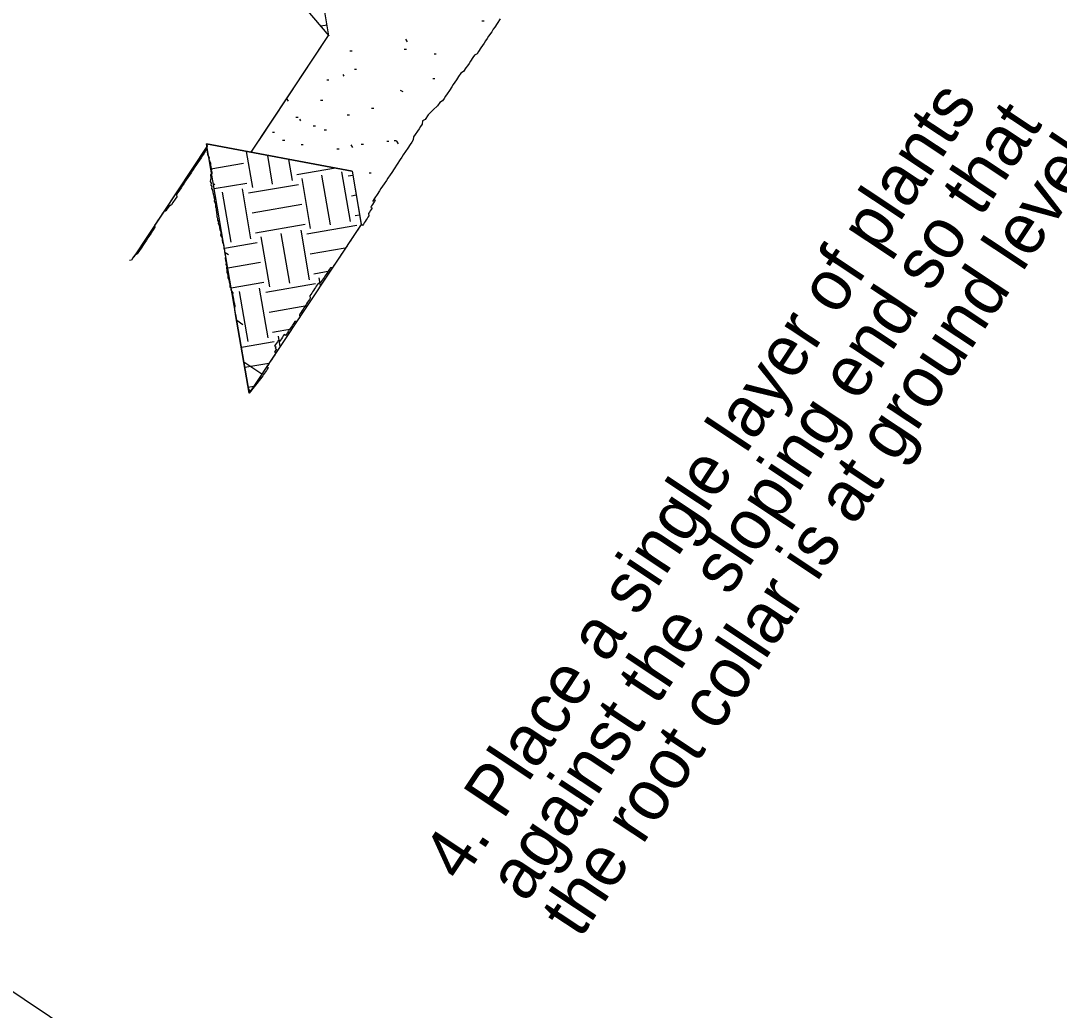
# Model space of a CAD drawing. Extents: x 561231 to 564240, y 590260 to 602519.
# Drawn here: x 563486.4 to 563562.9, y 590508.2 to 590581 of the extents above; entities that cross this region are included whole.
import ezdxf

# ---------------------------------------------------------------- set-up
doc = ezdxf.new("R2010")
doc.units = 0
doc.layers.add('Old_Level_1', color=7, linetype='Continuous')

msp = doc.modelspace()

# ---------------------------------------------------------------- linework, layer by layer
at = {"layer": 'Old_Level_1'}
for p, q in [((563509.071, 590579.938), (563501.981, 590621.124)), ((563509.071, 590579.938), (563501.981, 590621.124)), ((563496.058, 590595.222), (563509.071, 590579.938)), ((563520.329, 590581.03), (563520.495, 590581.03)), ((563508.372, 590580.744), (563508.372, 590580.745)), ((563508.935, 590580.727), (563508.469, 590580.646)), ((563503.345, 590571.354), (563509.043, 590579.944)), ((563503.908, 590572.202), (563509.047, 590579.95)), ((563503.908, 590572.202), (563509.047, 590579.95)), ((563509.062, 590579.95), (563509.071, 590579.938)), ((563509.062, 590579.95), (563509.071, 590579.938)), ((563509.065, 590579.929), (563509.065, 590579.93)), ((563509.065, 590579.93), (563509.065, 590579.929)), ((563514.858, 590579.495), (563514.737, 590579.686)), ((563510.61, 590578.824), (563510.775, 590578.824)), ((563514.612, 590578.945), (563514.778, 590578.945)), ((563516.814, 590578.599), (563516.979, 590578.6)), ((563510.187, 590576.967), (563510.106, 590577.095)), ((563510.945, 590577.467), (563511.11, 590577.467)), ((563508.904, 590576.702), (563509.069, 590576.702)), ((563516.711, 590576.789), (563516.877, 590576.789)), ((563514.319, 590575.938), (563514.503, 590575.844)), ((563506.096, 590575.124), (563505.974, 590575.315)), ((563508.448, 590575.188), (563508.614, 590575.188)), ((563506.632, 590573.934), (563506.797, 590573.934)), ((563510.418, 590574.105), (563510.583, 590574.105)), ((563512.213, 590574.611), (563512.379, 590574.61)), ((563507.011, 590573.664), (563506.931, 590573.791)), ((563507.918, 590573.303), (563508.084, 590573.304)), ((563504.9, 590572.836), (563505.065, 590572.837)), ((563508.715, 590573.021), (563508.88, 590573.021)), ((563500.077, 590571.764), (563494.701, 590563.659)), ((563500.083, 590571.773), (563494.707, 590563.668)), ((563500.083, 590571.773), (563494.707, 590563.668)), ((563503.193, 590553.625), (563500.055, 590571.97)), ((563500.055, 590571.97), (563510.776, 590569.961)), ((563510.776, 590569.961), (563500.055, 590571.97)), ((563505.648, 590572.254), (563505.813, 590572.254)), ((563507.012, 590571.937), (563507.178, 590571.938)), ((563510.824, 590571.712), (563510.703, 590571.903)), ((563511.447, 590571.947), (563511.612, 590571.946)), ((563513.323, 590572.178), (563513.488, 590572.178)), ((563513.884, 590572.224), (563514.049, 590572.225)), ((563514.196, 590571.981), (563514.074, 590572.171)), ((563503.456, 590568.765), (563502.999, 590571.418)), ((563504.923, 590569.018), (563504.56, 590571.126)), ((563509.651, 590571.611), (563509.817, 590571.611)), ((563502.774, 590570.536), (563500.371, 590570.122)), ((563506.389, 590569.271), (563506.12, 590570.833)), ((563509.544, 590570.191), (563506.693, 590569.7)), ((563507.723, 590565.751), (563507.091, 590569.418)), ((563509.19, 590566.004), (563508.558, 590569.671)), ((563510.656, 590566.257), (563510.025, 590569.923)), ((563510.827, 590569.657), (563510.486, 590569.598)), ((563510.776, 590569.961), (563511.434, 590566.049)), ((563510.782, 590569.97), (563511.44, 590566.058)), ((563510.782, 590569.97), (563511.44, 590566.058)), ((563512.021, 590569.845), (563512.186, 590569.845)), ((563500.554, 590569.053), (563500.657, 590568.985)), ((563503.026, 590569.069), (563500.622, 590568.655)), ((563503.323, 590564.993), (563502.691, 590568.66)), ((563506.819, 590568.967), (563503.153, 590568.335)), ((563501.856, 590564.741), (563501.224, 590568.408)), ((563511.074, 590568.19), (563510.738, 590568.132)), ((563507.072, 590567.501), (563503.405, 590566.869)), ((563511.321, 590566.722), (563510.991, 590566.665)), ((563511.434, 590566.049), (563503.193, 590553.625)), ((563507.324, 590566.034), (563503.658, 590565.402)), ((563507.648, 590561.964), (563507.017, 590565.63)), ((563511.113, 590565.958), (563507.447, 590565.327)), ((563504.715, 590561.458), (563504.084, 590565.124)), ((563506.182, 590561.711), (563505.55, 590565.377)), ((563503.78, 590564.695), (563501.37, 590564.28)), ((563510.276, 590564.304), (563507.699, 590563.86)), ((563501.421, 590563.98), (563501.664, 590563.819)), ((563504.033, 590563.228), (563501.621, 590562.812)), ((563509.145, 590562.599), (563507.951, 590562.393)), ((563504.285, 590561.762), (563501.872, 590561.346)), ((563508.447, 590561.547), (563508.35, 590562.11)), ((563503.115, 590557.434), (563502.484, 590561.1)), ((563504.581, 590557.686), (563503.95, 590561.353)), ((563508.078, 590561.66), (563504.411, 590561.028)), ((563507.449, 590560.041), (563504.664, 590559.562)), ((563502.276, 590558.982), (563502.723, 590558.686)), ((563506.318, 590558.337), (563504.917, 590558.095)), ((563505.038, 590557.388), (563502.62, 590556.971)), ((563505.472, 590557.061), (563505.342, 590557.817)), ((563502.8, 590555.923), (563504.131, 590555.04)), ((563504.641, 590555.809), (563502.871, 590555.504)), ((563503.51, 590554.104), (563503.122, 590554.037)), ((563503.144, 590553.909), (563503.309, 590553.8))]:
    msp.add_line(p, q, dxfattribs=at)
msp.add_lwpolyline([(563698.589, 591448.685), (563200.53, 590699.06), (563725.267, 590350.419), (564223.327, 591100.044)], close=True, dxfattribs=at)
for points in [[(563521.683, 590581.178), (563521.457, 590580.837), (563521.286, 590580.58), (563521.173, 590580.41), (563521.06, 590580.238), (563520.833, 590579.897), (563520.72, 590579.726), (563520.607, 590579.555), (563520.494, 590579.385), (563520.38, 590579.214), (563520.267, 590579.043), (563520.097, 590578.787), (563519.984, 590578.617), (563519.785, 590578.502), (563519.672, 590578.332), (563519.502, 590578.075), (563519.389, 590577.905), (563519.275, 590577.734), (563519.162, 590577.563), (563518.992, 590577.307), (563518.793, 590577.193), (563518.623, 590576.937), (563518.454, 590576.681), (563518.34, 590576.51), (563518.227, 590576.339), (563518.114, 590576.168), (563517.944, 590575.912), (563517.774, 590575.656), (563517.661, 590575.485), (563517.548, 590575.315), (563517.434, 590575.144), (563517.235, 590575.029), (563517.065, 590574.773), (563516.754, 590574.489), (563516.385, 590574.118), (563516.158, 590573.777), (563515.96, 590573.663), (563515.932, 590573.436), (563515.818, 590573.264), (563515.705, 590573.094), (563515.592, 590572.923), (563515.422, 590572.667), (563515.309, 590572.496), (563515.281, 590572.269), (563515.168, 590572.098), (563515.055, 590571.928), (563514.884, 590571.671), (563514.714, 590571.415), (563514.545, 590571.159), (563514.431, 590570.988), (563514.318, 590570.817), (563514.092, 590570.476), (563513.865, 590570.134), (563513.695, 590569.878), (563513.582, 590569.707), (563513.412, 590569.451), (563513.299, 590569.28), (563513.128, 590569.024), (563512.902, 590568.683), (563512.789, 590568.512), (563512.619, 590568.255), (563512.449, 590568), (563512.279, 590567.744)], [(563500.083, 590571.773), (563499.988, 590571.47), (563499.875, 590571.299), (563499.761, 590571.129), (563499.648, 590570.958), (563499.535, 590570.787), (563499.422, 590570.616), (563499.308, 590570.445), (563499.195, 590570.275), (563499.025, 590570.019), (563498.912, 590569.848), (563498.799, 590569.677), (563498.686, 590569.506), (563498.516, 590569.25), (563498.402, 590569.079), (563498.289, 590568.909), (563498.176, 590568.738), (563498.062, 590568.567), (563497.949, 590568.396), (563497.836, 590568.225), (563497.865, 590568.083), (563497.752, 590567.913), (563497.582, 590567.657), (563497.468, 590567.486), (563497.27, 590567.372), (563497.156, 590567.201), (563497.043, 590567.03), (563496.901, 590567.002), (563496.788, 590566.831), (563496.675, 590566.66), (563496.561, 590566.489), (563496.448, 590566.319), (563496.335, 590566.148), (563496.221, 590565.977), (563496.25, 590565.835), (563496.08, 590565.579), (563495.967, 590565.408), (563495.854, 590565.237), (563495.741, 590565.066), (563495.627, 590564.896), (563495.514, 590564.725), (563495.401, 590564.554), (563495.231, 590564.298), (563495.117, 590564.127), (563494.947, 590563.871), (563494.749, 590563.757), (563494.636, 590563.587), (563494.522, 590563.415), (563494.38, 590563.386), (563494.38, 590563.386)], [(563500.055, 590571.97), (563500.098, 590571.837), (563500.082, 590571.701), (563500.065, 590571.565), (563500.099, 590571.397), (563500.133, 590571.227), (563500.167, 590571.059), (563500.235, 590570.94), (563500.219, 590570.805), (563500.287, 590570.687), (563500.355, 590570.568), (563500.339, 590570.433), (563500.373, 590570.264), (563500.407, 590570.095), (563500.39, 590569.959), (563500.458, 590569.841), (563500.357, 590569.689), (563500.358, 590569.469), (563500.342, 590569.333), (563500.325, 590569.198), (563500.393, 590569.08), (563500.376, 590568.944), (563500.444, 590568.827), (563500.427, 590568.691), (563500.496, 590568.573), (563500.529, 590568.404), (563500.564, 590568.235), (563500.598, 590568.066), (563500.633, 590567.897), (563500.616, 590567.761), (563500.684, 590567.643), (563500.718, 590567.474), (563500.702, 590567.339), (563500.77, 590567.22), (563500.753, 590567.085), (563500.787, 590566.916), (563500.822, 590566.747), (563500.805, 590566.611), (563500.873, 590566.493), (563500.856, 590566.358), (563500.924, 590566.239), (563500.908, 590566.104), (563500.976, 590565.986), (563501.01, 590565.817), (563501.044, 590565.647), (563501.112, 590565.53), (563501.096, 590565.394), (563501.08, 590565.259), (563501.147, 590565.141), (563501.215, 590565.022), (563501.199, 590564.887), (563501.233, 590564.718), (563501.301, 590564.6), (563501.335, 590564.43), (563501.318, 590564.295), (563501.387, 590564.177), (563501.371, 590564.042), (563501.404, 590563.873), (563501.439, 590563.703), (563501.422, 590563.568), (563501.456, 590563.399), (563501.491, 590563.23), (563501.474, 590563.095), (563501.542, 590562.976), (563501.525, 590562.841), (563501.559, 590562.672), (563501.543, 590562.537), (563501.628, 590562.334), (563501.629, 590562.114), (563501.697, 590561.996), (563501.731, 590561.826), (563501.765, 590561.658), (563501.766, 590561.438), (563501.868, 590561.37), (563501.851, 590561.235), (563501.919, 590561.116), (563501.987, 590560.998), (563501.97, 590560.863), (563502.004, 590560.694), (563502.039, 590560.525), (563502.073, 590560.356), (563502.108, 590560.187), (563502.142, 590560.018), (563502.125, 590559.882), (563502.108, 590559.747), (563502.143, 590559.578), (563502.177, 590559.409), (563503.193, 590553.625), (563503.193, 590553.625), (563502.177, 590559.409)], [(563512.449, 590568), (563512.382, 590567.895), (563512.484, 590567.827), (563512.417, 590567.725), (563512.349, 590567.624), (563512.281, 590567.522), (563512.214, 590567.421), (563512.147, 590567.319), (563512.248, 590567.251), (563512.181, 590567.15), (563512.114, 590567.048), (563512.046, 590566.947), (563511.978, 590566.845), (563512.013, 590566.676), (563511.946, 590566.574), (563511.878, 590566.473), (563511.811, 590566.371), (563511.743, 590566.269), (563511.676, 590566.168), (563511.609, 590566.067), (563511.541, 590565.964), (563511.439, 590566.032), (563511.372, 590565.93), (563511.305, 590565.829), (563511.237, 590565.728), (563511.169, 590565.626), (563511.102, 590565.524), (563511.035, 590565.422), (563510.968, 590565.321), (563510.9, 590565.219), (563510.833, 590565.117), (563510.765, 590565.016), (563510.698, 590564.914), (563510.631, 590564.813), (563510.563, 590564.711), (563510.495, 590564.61), (563510.428, 590564.508), (563510.361, 590564.406), (563510.293, 590564.305), (563510.226, 590564.203), (563510.159, 590564.101), (563510.091, 590564), (563510.024, 590563.898), (563509.956, 590563.796), (563509.889, 590563.695), (563509.822, 590563.594), (563509.754, 590563.492), (563509.687, 590563.39), (563509.619, 590563.288), (563509.552, 590563.187), (563509.484, 590563.085), (563509.417, 590562.983), (563509.35, 590562.882), (563509.181, 590562.848), (563509.114, 590562.746), (563509.046, 590562.644), (563508.978, 590562.543), (563508.911, 590562.441), (563508.844, 590562.34), (563508.776, 590562.238), (563508.709, 590562.136), (563508.642, 590562.035), (563508.574, 590561.933), (563508.507, 590561.831), (563508.439, 590561.729), (563508.27, 590561.696), (563508.203, 590561.594), (563508.135, 590561.492), (563508.068, 590561.39), (563508, 590561.289), (563507.933, 590561.188), (563507.866, 590561.086), (563507.798, 590560.984), (563507.731, 590560.883), (563507.663, 590560.781), (563507.698, 590560.612), (563507.63, 590560.51), (563507.563, 590560.408), (563507.495, 590560.307), (563507.428, 590560.206), (563507.361, 590560.104), (563507.293, 590560.002), (563507.226, 590559.9), (563507.159, 590559.799), (563507.091, 590559.697), (563507.024, 590559.595), (563506.956, 590559.494), (563506.889, 590559.392), (563506.923, 590559.224), (563506.856, 590559.122), (563506.788, 590559.02), (563506.721, 590558.918), (563506.552, 590558.884), (563506.484, 590558.782), (563506.417, 590558.681), (563506.35, 590558.579), (563506.283, 590558.478), (563506.215, 590558.377), (563506.147, 590558.275), (563506.08, 590558.173), (563506.012, 590558.071)], [(563506.012, 590558.071), (563506.012, 590558.071), (563505.945, 590557.97), (563505.878, 590557.868), (563505.776, 590557.936), (563505.708, 590557.834), (563505.641, 590557.732), (563505.574, 590557.631), (563505.507, 590557.529), (563505.439, 590557.427), (563505.337, 590557.495), (563505.27, 590557.393), (563505.203, 590557.291), (563505.135, 590557.19), (563505.068, 590557.089), (563505.169, 590557.021), (563505.102, 590556.919), (563505.204, 590556.852), (563505.136, 590556.75), (563505.069, 590556.649), (563505.17, 590556.581), (563505.103, 590556.48), (563505.035, 590556.378), (563504.968, 590556.277), (563504.9, 590556.175), (563504.833, 590556.073), (563504.766, 590555.972), (563504.698, 590555.87), (563504.631, 590555.768), (563504.564, 590555.667), (563504.496, 590555.566), (563504.598, 590555.498), (563504.53, 590555.396), (563504.463, 590555.294), (563504.396, 590555.193), (563504.329, 590555.091), (563504.261, 590554.99), (563504.194, 590554.888), (563504.126, 590554.786), (563503.193, 590553.625), (563503.193, 590553.625), (563504.126, 590554.786)]]:
    msp.add_lwpolyline(points, dxfattribs=at)

# ---------------------------------------------------------------- texts
for s, p in [('4. Place a single layer of plants ', (563518.834, 590517.51)), (' against the  sloping end so that ', (563522.821, 590514.865)), (' the root collar is at ground level.', (563526.807, 590512.221))]:
    msp.add_text(s, height=3.72047, rotation=56.44242, dxfattribs=at).set_placement(p)

doc.saveas('drawing.dxf')
